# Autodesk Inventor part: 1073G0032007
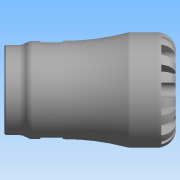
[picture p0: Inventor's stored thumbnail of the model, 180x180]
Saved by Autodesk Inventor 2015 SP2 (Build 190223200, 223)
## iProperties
Created: 2016-12
Part Number: 1073G0032007
Material: Generic
Description: PLASSON FEMALE INTEGRAL BRASS THREAD 32X3/4" G SERIES 1
Document SubType Name: Modeling
Designer: KIM
Density: 1 g/cm^3
Appearance: Default
Author: KIM
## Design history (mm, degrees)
derived "1073G.ipt"
feature "Solid1::1073G.ipt"
tag "TaggingFeature1"
body "Solid1"
other parameters: "d0" = 86, "d1" = 23.52, "d2" = 32, "d4" = 58, "d6" = 56, "d8" = 49.3, "d13" = 7.2, "d14" = 7.2, "d15" = 0, "d17" = 360 deg, "d19" = 8 deg, "d20" = 0.64, "d21" = 0.64, "d22" = 8 deg, "d24" = 0, "d26" = 360 deg, "d32" = 5.8, "d33" = 5.8, "d39" = 0.72351, "d42" = 24.117, "d43" = 45.24, "d46" = 2.66667, "d47" = 12, "d48" = 22.91115, "d50" = 5.94, "d51" = 0.58, "d54" = 11.2, "d55" = 7.04, "d57" = 14.112, "d58" = 0, "d68" = 360 deg, "d72" = 0.64, "d74" = 0, "d76" = 9.52, "d_" = 32, "E_" = 58, "H_" = 86, "l_" = 56, "G_" = 24.117, "l_2" = 12, "d9" = 9, "d11" = 58, "d49" = 18
